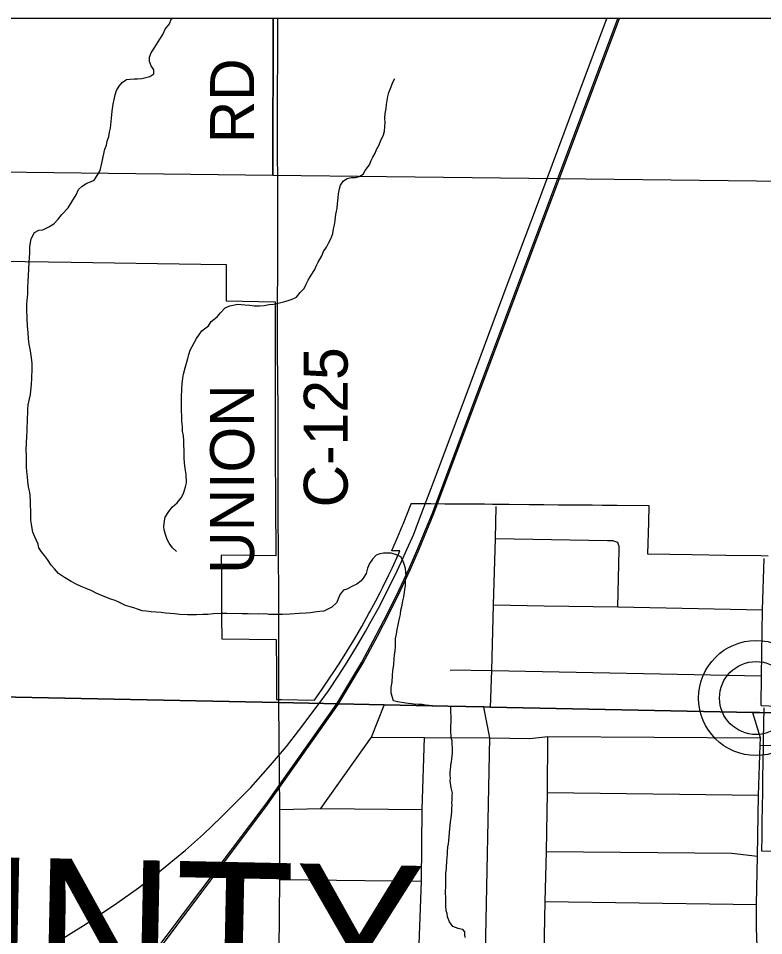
# Model space of a CAD drawing. Extents: x -7.3 to 34, y 0 to 22.
# Drawn here: x 5.466 to 6.43, y 19.714 to 20.9 of the extents above; entities that cross this region are included whole.
import ezdxf

# ---------------------------------------------------------------- set-up
doc = ezdxf.new("R2010")
doc.units = 0
for name, color, linetype in [('GM_X_City_Street', 7, 'Continuous'), ('GM_X_Corporation', 7, 'Continuous'), ('GM_X_County_Road', 7, 'Continuous'), ('GM_X_County_Road_Text', 7, 'Continuous'), ('GM_X_County_Text', 7, 'Continuous'), ('GM_X_Minor_River', 7, 'Continuous'), ('GM_X_Rail_Line', 7, 'Continuous'), ('GM_X_Township_Road', 7, 'Continuous'), ('GM_X_Unincorporated', 7, 'Continuous'), ('GM_X_Unincorporated_Location', 7, 'Continuous')]:
    doc.layers.add(name, color=color, linetype=linetype)

msp = doc.modelspace()

# ---------------------------------------------------------------- linework, layer by layer
at = {"layer": 'GM_X_City_Street'}
for p, q in [((6.1499, 19.8991), (6.4231, 19.8958)), ((5.8038, 19.7866), (5.987, 19.7844)), ((6.147, 19.7582), (6.4205, 19.7541))]:
    msp.add_line(p, q, dxfattribs=at)
for points in [[(6.0765, 20.0091), (6.078, 20.0568), (6.0801, 20.1416), (6.0827, 20.2271), (6.0836, 20.2687)], [(6.2412, 20.139), (6.2427, 20.2128), (6.2426, 20.217), (6.2412, 20.2221), (6.2346, 20.2245), (6.2276, 20.2244), (6.0827, 20.2271)], [(6.0801, 20.1416), (6.1457, 20.1405), (6.2412, 20.139), (6.4282, 20.1351)], [(6.0241, 20.0575), (6.078, 20.0568), (6.4267, 20.0499)], [(5.8032, 19.6948), (5.8038, 19.7866), (5.8041, 19.8769), (5.8027, 20.0147)], [(5.8568, 19.8782), (5.9224, 19.9706), (5.939, 20.0119)], [(6.0699, 19.6913), (6.0755, 19.9696), (6.0679, 20.0093)], [(5.9224, 19.9706), (5.9911, 19.9702), (6.0755, 19.9696), (6.1272, 19.969), (6.1507, 19.9714), (6.4253, 19.9698)], [(5.9838, 19.6915), (5.987, 19.7844), (5.9882, 19.8772), (5.9911, 19.9702)], [(6.1458, 19.6913), (6.147, 19.7582), (6.1486, 19.8227), (6.1499, 19.8991), (6.1507, 19.9714)], [(5.8041, 19.8769), (5.8568, 19.8782), (5.9882, 19.8772)], [(6.1486, 19.8227), (6.3883, 19.8205), (6.4216, 19.8166)]]:
    msp.add_lwpolyline(points, dxfattribs=at)
at = {"layer": 'GM_X_Corporation'}
for points in [[(2.7422, 20.0783), (4.2288, 20.048), (4.2328, 20.0479), (4.4762, 20.0428), (4.7954, 20.036), (4.9235, 20.0334), (4.9401, 20.0331), (4.9519, 20.0328), (5.8024, 20.0153), (5.9388, 20.0125), (6.0214, 20.0108), (6.0677, 20.0098), (6.0763, 20.0096), (6.4154, 20.0027), (6.4242, 20.0024), (6.9507, 19.9888), (6.9988, 19.9839), (7.6051, 19.9224), (7.8469, 19.8978), (8.8913, 19.7872), (8.9, 19.7858), (8.9, 20.9), (2.1, 20.9)], [(8.9, 20.9), (4.7796, 20.9), (4.7799, 20.7827), (4.7788, 20.7319), (4.7788, 20.7252), (4.7798, 20.7211), (4.7847, 20.7149), (4.7927, 20.7114), (4.804, 20.71), (4.7977, 20.2101), (4.7954, 20.036), (4.9235, 20.0334), (4.9401, 20.0331), (4.9519, 20.0328), (5.8024, 20.0153), (5.9388, 20.0125), (6.0214, 20.0108), (6.0677, 20.0098), (6.0763, 20.0096), (6.4154, 20.0027), (6.4242, 20.0024), (6.9507, 19.9888), (6.9988, 19.9839), (7.6051, 19.9224)], [(5.4343, 20.586), (5.4746, 20.5855), (5.505, 20.585), (5.5343, 20.5846), (5.7016, 20.5823), (5.7346, 20.5819), (5.7347, 20.5346), (5.7979, 20.5336), (5.7979, 20.4728), (5.7979, 20.4459), (5.7979, 20.4255), (5.7981, 20.3286), (5.7982, 20.2841), (5.7982, 20.2758), (5.7983, 20.262), (5.7985, 20.2483), (5.7986, 20.2315), (5.7988, 20.2051), (5.7988, 20.205), (5.7682, 20.2054), (5.7282, 20.2059), (5.7284, 20.1698), (5.7284, 20.1599), (5.7286, 20.1375), (5.7286, 20.1338), (5.7286, 20.1247), (5.7288, 20.0978), (5.7993, 20.097), (5.7996, 20.0538), (5.7997, 20.0195), (5.7997, 20.0194), (5.8023, 20.0193), (5.8026, 20.0193), (5.8029, 20.0193), (5.806, 20.0193), (5.8487, 20.0185), (5.8595, 20.0339), (5.8701, 20.0495), (5.8728, 20.0536), (5.8805, 20.0653), (5.8905, 20.0813), (5.8973, 20.0924), (5.9003, 20.0975), (5.9098, 20.1138), (5.919, 20.1303), (5.9202, 20.1325), (5.9279, 20.147), (5.9335, 20.1577), (5.9366, 20.1638), (5.9449, 20.1807), (5.9486, 20.1884), (5.949, 20.1893), (5.9573, 20.2074), (5.9591, 20.2115), (5.9591, 20.2115), (5.9487, 20.2117), (5.9488, 20.2118), (5.9549, 20.2259), (5.9562, 20.2288), (5.9627, 20.2444), (5.9634, 20.2462), (5.9736, 20.2723), (5.9739, 20.2729), (5.9991, 20.2727), (6.0171, 20.2725), (6.0395, 20.2723), (6.0411, 20.2723), (6.0685, 20.2721), (6.079, 20.272), (6.0885, 20.2719), (6.1005, 20.2718), (6.1264, 20.2715), (6.1453, 20.2713), (6.1643, 20.2712), (6.1832, 20.271), (6.1894, 20.2709), (6.2021, 20.2708), (6.208, 20.2708), (6.2211, 20.2706), (6.24, 20.2705), (6.2813, 20.2701), (6.2807, 20.2483), (6.2795, 20.2077), (6.2795, 20.2076), (6.3372, 20.2067), (6.3805, 20.206), (6.4261, 20.2053), (6.4261, 20.2054), (6.4355, 20.2051)], [(8.9, 14.1), (8.9, 19.7858), (8.8913, 19.7872), (7.8469, 19.8978), (7.6051, 19.9224), (6.9988, 19.9839), (6.9507, 19.9888), (6.4242, 20.0024), (6.4154, 20.0027), (6.0763, 20.0096), (6.0677, 20.0098), (6.0214, 20.0108), (5.9388, 20.0125), (5.8024, 20.0153), (4.9519, 20.0328), (4.9401, 20.0331), (4.9235, 20.0334), (4.7954, 20.036), (4.4762, 20.0428), (4.2328, 20.0479), (4.2288, 20.048), (2.7422, 20.0783)], [(8.9, 19.3924), (8.9, 19.7858), (8.8913, 19.7872), (7.8469, 19.8978), (7.6051, 19.9224), (6.9988, 19.9839), (6.9507, 19.9888), (6.4242, 20.0024), (6.4154, 20.0027), (6.0763, 20.0096), (6.0677, 20.0098), (6.0214, 20.0108), (5.9388, 20.0125), (5.8024, 20.0153), (4.9519, 20.0328), (4.9401, 20.0331), (4.9235, 20.0334), (4.7954, 20.036), (4.4762, 20.0428), (4.2328, 20.0479), (4.2288, 20.048), (2.7422, 20.0783)], [(6.4298, 20.0087), (6.4291, 19.9675), (6.429, 19.958), (6.4286, 19.9372), (6.4283, 19.9183), (6.428, 19.8993), (6.4277, 19.8804), (6.4274, 19.8614), (6.4271, 19.8425), (6.4268, 19.8236), (6.468, 19.8228)]]:
    msp.add_lwpolyline(points, dxfattribs=at)
for points in [[(5.7954, 20.9), (4.7758, 20.9), (4.7738, 20.7095), (4.8034, 20.7092), (5.7947, 20.6973)], [(6.7635, 20.9), (5.7954, 20.9), (5.7947, 20.6973), (6.6043, 20.6878), (6.582, 20.6935), (6.5606, 20.7031), (6.5544, 20.713), (6.5532, 20.7286), (6.5544, 20.7513), (6.5566, 20.7672), (6.5602, 20.7781), (6.5686, 20.7953), (6.5902, 20.8184), (6.6168, 20.8406), (6.6463, 20.8574), (6.6746, 20.8693), (6.7111, 20.8773), (6.7537, 20.8848)]]:
    msp.add_lwpolyline(points, close=True, dxfattribs=at)
at = {"layer": 'GM_X_County_Road'}
for points in [[(5.8027, 20.0147), (5.8028, 20.1547), (5.8018, 20.2599), (5.8018, 20.3934), (5.8009, 20.4703), (5.8012, 20.6375), (5.8009, 20.7796), (5.8012, 20.8752), (5.8014, 20.9)], [(6.4262, 20.0115), (6.4267, 20.0499), (6.4282, 20.1351), (6.4303, 20.2018)]]:
    msp.add_lwpolyline(points, dxfattribs=at)
at = {"layer": 'GM_X_Minor_River'}
for points in [[(5.6055, 20.8208), (5.6105, 20.8214), (5.6155, 20.8216), (5.62, 20.8218), (5.6254, 20.8224), (5.6308, 20.8234), (5.6358, 20.8248), (5.6412, 20.8281), (5.641, 20.8334), (5.6377, 20.8388), (5.6352, 20.8442), (5.6354, 20.8499), (5.6375, 20.8555), (5.6423, 20.8629), (5.6487, 20.873), (5.6527, 20.8793), (5.6555, 20.8861), (5.6611, 20.8931), (5.6635, 20.8991), (5.6648, 20.9)], [(5.5663, 20.1569), (5.5607, 20.1597), (5.5535, 20.1629), (5.5471, 20.1654), (5.5407, 20.1686), (5.5339, 20.1719), (5.5253, 20.1771), (5.5178, 20.1822), (5.5127, 20.1881), (5.5083, 20.1931), (5.5035, 20.2001), (5.4998, 20.2055), (5.4958, 20.2102), (5.4925, 20.2156), (5.4915, 20.2202), (5.4894, 20.2248), (5.4872, 20.2298), (5.4847, 20.2356), (5.4837, 20.2406), (5.4827, 20.2459), (5.4821, 20.2512), (5.4819, 20.2569), (5.4821, 20.2634), (5.4816, 20.2702), (5.4817, 20.2752), (5.4812, 20.2835), (5.4802, 20.2892), (5.4788, 20.2942), (5.4779, 20.3018), (5.4777, 20.3072), (5.4767, 20.314), (5.4765, 20.3201), (5.4764, 20.3266), (5.4762, 20.3342), (5.4761, 20.3425), (5.4766, 20.3592), (5.4772, 20.3664), (5.4777, 20.3835), (5.4779, 20.3895), (5.478, 20.3941), (5.4785, 20.4001), (5.4803, 20.4081), (5.4816, 20.4137), (5.4821, 20.4186), (5.4828, 20.4266), (5.4834, 20.4342), (5.4838, 20.4474), (5.4836, 20.4543), (5.4824, 20.4642), (5.4814, 20.4703), (5.4797, 20.4787), (5.4788, 20.4855), (5.4783, 20.4939), (5.4778, 20.5019), (5.4773, 20.5118), (5.4769, 20.5236), (5.4767, 20.5308), (5.4779, 20.5436), (5.4781, 20.5524), (5.4787, 20.5592), (5.4792, 20.5755), (5.4798, 20.5846), (5.4806, 20.5963), (5.4808, 20.6047), (5.4814, 20.61), (5.4823, 20.6149), (5.4867, 20.6231), (5.4925, 20.626), (5.4975, 20.6266), (5.5052, 20.6305), (5.5115, 20.6345), (5.5174, 20.6404), (5.5221, 20.6463), (5.5304, 20.6552), (5.5348, 20.6627), (5.5404, 20.6716), (5.5437, 20.6787), (5.5484, 20.6831), (5.5542, 20.6871), (5.5592, 20.6885), (5.5639, 20.6907), (5.5687, 20.6981), (5.5715, 20.7033), (5.5737, 20.7128), (5.5755, 20.7211), (5.5777, 20.7309), (5.5797, 20.7361), (5.5806, 20.7414), (5.5827, 20.7474), (5.5837, 20.7527), (5.585, 20.758), (5.5855, 20.7625), (5.5861, 20.7708), (5.5871, 20.7799), (5.5885, 20.789), (5.5895, 20.795), (5.5912, 20.8011), (5.5929, 20.8067), (5.5961, 20.8123), (5.6001, 20.8171), (5.6055, 20.8208)], [(5.9322, 20.7363), (5.9343, 20.7412), (5.938, 20.7494), (5.9393, 20.7543), (5.9398, 20.76), (5.94, 20.7653), (5.9397, 20.7703), (5.9403, 20.7771), (5.9413, 20.7835), (5.9418, 20.7888), (5.9427, 20.7937), (5.9436, 20.799), (5.945, 20.8043), (5.947, 20.8095), (5.9499, 20.8174), (5.9527, 20.8222)], [(5.6702, 20.2107), (5.6653, 20.2154), (5.6609, 20.2216), (5.6584, 20.2263), (5.6559, 20.2328), (5.6542, 20.2385), (5.654, 20.2431), (5.6549, 20.2503), (5.6558, 20.2552), (5.6602, 20.2623), (5.665, 20.2682), (5.6713, 20.2737), (5.6764, 20.28), (5.6793, 20.2856), (5.6818, 20.2943), (5.6831, 20.2996), (5.6827, 20.3102), (5.6817, 20.3178), (5.6808, 20.3251), (5.6802, 20.3312), (5.6804, 20.3365), (5.6802, 20.3418), (5.68, 20.3482), (5.6798, 20.3543), (5.6792, 20.3604), (5.6782, 20.3661), (5.678, 20.3722), (5.6771, 20.3791), (5.6773, 20.3855), (5.6767, 20.3924), (5.677, 20.4011), (5.6768, 20.4095), (5.6772, 20.4212), (5.6777, 20.4273), (5.6787, 20.4348), (5.6793, 20.4398), (5.6814, 20.448), (5.6848, 20.4601), (5.6861, 20.4654), (5.6882, 20.471), (5.6963, 20.4859), (5.6999, 20.4915), (5.7031, 20.496), (5.7116, 20.5026), (5.7152, 20.5082), (5.7231, 20.514), (5.7274, 20.5192), (5.7333, 20.5255), (5.7395, 20.5283), (5.7495, 20.5303), (5.7541, 20.5302), (5.7586, 20.5296), (5.7651, 20.5291), (5.7708, 20.5285), (5.7777, 20.5283), (5.7838, 20.5289), (5.7903, 20.5302), (5.7956, 20.5304), (5.8033, 20.5321), (5.8102, 20.5338), (5.8149, 20.5352), (5.8199, 20.5369), (5.8257, 20.5394), (5.8304, 20.5454), (5.8352, 20.5505), (5.838, 20.5561), (5.8404, 20.5614), (5.8436, 20.5666), (5.8492, 20.5752), (5.8509, 20.5797), (5.8533, 20.5849), (5.8582, 20.5931), (5.8606, 20.5987), (5.8642, 20.6043), (5.867, 20.6092), (5.8699, 20.6148), (5.8724, 20.6219), (5.8733, 20.628), (5.8746, 20.6329), (5.8755, 20.6382), (5.8761, 20.6438), (5.877, 20.6487), (5.8779, 20.6544), (5.8785, 20.6601), (5.8795, 20.668), (5.88, 20.6733), (5.8813, 20.6797), (5.8826, 20.6843), (5.8862, 20.6898), (5.8909, 20.6931), (5.8963, 20.6941), (5.902, 20.6943), (5.9066, 20.6957), (5.9117, 20.6986), (5.9145, 20.7031), (5.9197, 20.7105), (5.9221, 20.7161), (5.9242, 20.7206), (5.9274, 20.7258), (5.929, 20.7303), (5.9322, 20.7363)], [(6.025, 20.0103), (6.0062, 20.0107), (5.9969, 20.0117), (5.9923, 20.0118), (5.9878, 20.0127), (5.9832, 20.0128), (5.9775, 20.0134), (5.9669, 20.0144), (5.9562, 20.0163), (5.9509, 20.0176), (5.9478, 20.0275), (5.948, 20.0347), (5.949, 20.0415), (5.9496, 20.0503), (5.9502, 20.0563), (5.9512, 20.0646), (5.9518, 20.0722), (5.9523, 20.0768), (5.9529, 20.0824), (5.9534, 20.0874), (5.9537, 20.0983), (5.9546, 20.1036), (5.9556, 20.1097), (5.9569, 20.1157), (5.9582, 20.1221), (5.96, 20.1293), (5.9605, 20.1346), (5.9622, 20.1414), (5.9632, 20.1467), (5.9645, 20.1519), (5.9655, 20.161), (5.9664, 20.1667), (5.9666, 20.1739), (5.9672, 20.1784), (5.9669, 20.1837), (5.9663, 20.1887), (5.9649, 20.1941), (5.9632, 20.199), (5.9603, 20.2037), (5.955, 20.2065), (5.9478, 20.2086), (5.9433, 20.2087), (5.9379, 20.2085), (5.9333, 20.2075), (5.9287, 20.2058), (5.9236, 20.2006), (5.92, 20.195), (5.9175, 20.189), (5.9154, 20.1822), (5.9126, 20.1774), (5.909, 20.1729), (5.9035, 20.1685), (5.8981, 20.1657), (5.8907, 20.1621), (5.8861, 20.1607), (5.8818, 20.1555), (5.8793, 20.1495), (5.8776, 20.1446), (5.8714, 20.1387), (5.8659, 20.1359), (5.8609, 20.1337), (5.8556, 20.1331), (5.8487, 20.1322), (5.8437, 20.1312), (5.8379, 20.131), (5.8288, 20.1305), (5.8173, 20.1297), (5.8074, 20.1292), (5.8009, 20.1294), (5.7944, 20.1292), (5.7898, 20.1294), (5.7853, 20.1299), (5.7769, 20.1298), (5.7628, 20.1302), (5.7547, 20.13), (5.7353, 20.1306), (5.7277, 20.1305), (5.7181, 20.13), (5.7108, 20.1294), (5.7044, 20.1293), (5.696, 20.1287), (5.6845, 20.1287), (5.6746, 20.129), (5.6678, 20.13), (5.662, 20.1305), (5.656, 20.1311), (5.6503, 20.1316), (5.6438, 20.1322), (5.6377, 20.1327), (5.6312, 20.1333), (5.6259, 20.1339), (5.6199, 20.1359), (5.615, 20.138), (5.6104, 20.1389), (5.6044, 20.1409), (5.5965, 20.1446), (5.5912, 20.1474), (5.5855, 20.1491), (5.5776, 20.152), (5.5723, 20.1544), (5.5663, 20.1569)], [(6.0263, 19.8786), (6.0267, 19.8824), (6.0264, 19.8858), (6.0269, 19.8893), (6.027, 19.893), (6.027, 19.8957), (6.0271, 19.8984), (6.0264, 19.9018), (6.0257, 19.9052), (6.025, 19.9083), (6.0247, 19.911), (6.0244, 19.914), (6.0245, 19.9174), (6.0242, 19.9212), (6.0242, 19.925), (6.0247, 19.9292), (6.0252, 19.9326), (6.0252, 19.9353), (6.0261, 19.9383), (6.0265, 19.9425), (6.027, 19.9466), (6.0271, 19.9504), (6.0271, 19.9531), (6.0272, 19.9569), (6.0269, 19.9611), (6.0267, 19.966), (6.0256, 19.9698), (6.0253, 19.9733), (6.025, 19.9767), (6.0251, 19.9797), (6.0251, 19.9824), (6.0252, 19.9854), (6.0253, 19.9892), (6.0253, 19.9919), (6.0254, 19.9945), (6.0255, 19.9987), (6.0252, 20.0021), (6.0249, 20.0103)], [(6.0249, 20.0061), (6.0249, 20.0061)], [(6.0435, 19.7115), (6.0432, 19.7156), (6.0433, 19.7191), (6.0407, 19.7218), (6.038, 19.7222), (6.0346, 19.723), (6.0309, 19.7243), (6.0275, 19.7259), (6.0253, 19.7289), (6.0235, 19.732), (6.0209, 19.7382), (6.0203, 19.7424), (6.0192, 19.7462), (6.0186, 19.753), (6.0184, 19.7595), (6.0185, 19.7648), (6.0182, 19.7682), (6.0183, 19.772), (6.0184, 19.7762), (6.0184, 19.7804), (6.0185, 19.7846), (6.0186, 19.788), (6.0187, 19.7914), (6.0188, 19.7948), (6.0193, 19.8009), (6.0194, 19.8047), (6.0198, 19.8077), (6.0199, 19.8108), (6.0203, 19.8149), (6.0208, 19.8195), (6.0209, 19.8225), (6.0214, 19.8286), (6.0219, 19.8327), (6.0223, 19.8369), (6.0228, 19.8418), (6.0233, 19.8472), (6.0238, 19.8521), (6.0243, 19.8563), (6.0248, 19.8612), (6.0256, 19.8665), (6.0262, 19.8741), (6.0263, 19.8786)]]:
    msp.add_lwpolyline(points, dxfattribs=at)
at = {"layer": 'GM_X_Rail_Line'}
for points in [[(5.855, 20.0143), (5.8668, 20.0306), (5.8803, 20.0509), (5.891, 20.0674), (5.9043, 20.0897), (5.9146, 20.1074), (5.9203, 20.1177), (5.9316, 20.1375), (5.9528, 20.1794), (5.9611, 20.1976), (5.9682, 20.2134), (5.9771, 20.2332), (5.9833, 20.2494), (6.0027, 20.3004), (6.0448, 20.4128), (6.0979, 20.5555), (6.1357, 20.656), (6.1924, 20.8076), (6.227, 20.9)], [(5.8776, 20.0139), (5.91, 20.0675), (5.9285, 20.1023), (5.9437, 20.1313), (5.958, 20.1602), (5.9711, 20.1886), (5.9823, 20.2144), (5.9922, 20.2385), (6.0014, 20.2604), (6.0678, 20.4376), (6.2409, 20.9)], [(5.8793, 20.0129), (5.9116, 20.0666), (5.9302, 20.1014), (5.9454, 20.1305), (5.9597, 20.1593), (5.9728, 20.1878), (5.9841, 20.2136), (5.9939, 20.2378), (6.0031, 20.2597), (6.0696, 20.4369), (6.243, 20.9)], [(2.7405, 18.0079), (3.3109, 18.3572), (4.0313, 18.798), (4.702, 19.2088), (4.7774, 19.2546), (4.9109, 19.336), (5.2623, 19.5511), (5.5045, 19.6986), (5.5533, 19.7292), (5.593, 19.7558), (5.6212, 19.7759), (5.6461, 19.795), (5.6821, 19.8246), (5.7051, 19.845), (5.7282, 19.867), (5.7473, 19.8866), (5.7663, 19.9054), (5.7919, 19.9343), (5.8126, 19.9584), (5.8283, 19.9791), (5.855, 20.0143)], [(3.6345, 17.0151), (3.985, 17.4802), (4.3732, 17.9988), (4.5251, 18.2021), (4.7981, 18.5667), (5.0774, 18.9371), (5.1565, 19.0428), (5.1846, 19.0805), (5.2002, 19.101), (5.5499, 19.5711), (5.7863, 19.8846), (5.8776, 20.0139)], [(3.636, 17.0139), (3.9865, 17.479), (4.3757, 17.998), (4.5264, 18.1998), (4.796, 18.5597), (5.0789, 18.9359), (5.158, 19.0417), (5.1862, 19.0793), (5.2017, 19.0998), (5.5529, 19.5699), (5.7879, 19.8835), (5.8792, 20.0128)]]:
    msp.add_lwpolyline(points, dxfattribs=at)
at = {"layer": 'GM_X_Township_Road'}
for points in [[(6.4262, 20.0115), (6.5277, 20.0071), (6.6238, 20.0055), (6.6864, 20.0045)], [(6.4288, 19.6818), (6.4249, 19.6878), (6.4211, 19.7004), (6.4202, 19.7237), (6.4205, 19.7541), (6.4216, 19.8166), (6.4231, 19.8958), (6.4251, 19.9601), (6.4253, 19.9698), (6.4157, 20.0021)], [(6.4251, 19.9601), (6.5165, 19.959), (6.6098, 19.9576), (6.6829, 19.9576)]]:
    msp.add_lwpolyline(points, dxfattribs=at)
at = {"layer": 'GM_X_Unincorporated'}
for radius in [0.0744, 0.0472]:
    msp.add_circle((6.4198, 20.0212), radius, dxfattribs=at)
at = {"layer": 'GM_X_Unincorporated_Location'}
msp.add_line((6.4198, 20.0212), (6.4198, 20.0212), dxfattribs=at)

# ---------------------------------------------------------------- texts
at = {"layer": 'GM_X_County_Road_Text'}
for s, p in [('RD', (5.7706, 20.7385)), ('C-125', (5.8917, 20.2677)), ('UNION', (5.7706, 20.1819))]:
    msp.add_text(s, height=0.05682, rotation=90, dxfattribs=at).set_placement(p)
at = {"layer": 'GM_X_County_Text'}
msp.add_text('WARREN COUNTY', height=0.189394, rotation=358.8222, dxfattribs=at).set_placement((3.7242, 19.6612))

doc.saveas('drawing.dxf')
